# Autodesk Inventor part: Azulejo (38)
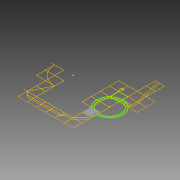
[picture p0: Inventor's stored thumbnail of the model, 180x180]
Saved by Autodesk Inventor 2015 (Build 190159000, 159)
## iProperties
Created: 2015-04
Part Number: Azulejo (38)
Material: Genérico
Document SubType Name: Modeling
Designer: Felipe
Density: 1 g/cm^3
Appearance: Padrão
Author: Felipe
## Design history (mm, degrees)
sketch "Sketch1"
  geometry: L1 (-1510, -7490)-(-1510, -6010); L2 (-3010, -1490)-(-3010, -10); L3 (-2990, 10)-(-1510, 10); L4 (-1510, -10)-(-2990, -10); L5 (-1510, -1490)-(-1510, -10); L6 (-1490, -10)-(-1490, -1490); L7 (-1490, -1490)-(-10, -1490); L8 (-10, -1510)-(-1490, -1510); L9 (-10, -2990)-(-10, -1510); L10 (-10, -5990)-(-10, -4510); L11 (-1490, -7490)-(-10, -7490); L12 (4490, -6010)-(3010, -6010); L13 (10, -1510)-(10, -2990); L14 (10, -3010)-(10, -4490); L15 (10, -4510)-(10, -5990); L16 (10, -5990)-(1490, -5990); L17 (1490, -6010)-(10, -6010); L18 (10, -7490)-(1490, -7490); L19 (1510, -5990)-(2990, -5990); L20 (2990, -6010)-(1510, -6010); L21 (1510, -7490)-(2990, -7490); L22 (4490, 1510)-(4490, 2990); L23 (4490, 10)-(4490, 1490); L24 (4490, -1490)-(4490, -10); L25 (4490, -2990)-(4490, -1510); L26 (3010, -5990)-(4490, -5990); L27 (3010, -7490)-(4490, -7490); L28 (4510, 3010)-(5990, 3010); L29 (5990, 2990)-(4510, 2990); L30 (4510, 2990)-(4510, 1510); L31 (4510, 1510)-(5990, 1510); L32 (5990, 1510)-(5990, 1740.185); L33 (5990, 1760.2)-(5990, 2259.8); L34 (5990, 2279.815)-(5990, 2990); L35 (5990, 1490)-(4510, 1490); L36 (4510, 1490)-(4510, 10); L37 (4510, 10)-(5990, 10); L38 (5990, 10)-(5990, 1490); L39 (5975.983, -10)-(4510, -10); L40 (4510, -10)-(4510, -1490); L41 (5990, -1510)-(5782.897, -1510); L42 (5782.897, -1510)-(5688.66, -1510); L43 (5668.66, -1510)-(5482.895, -1510); L44 (5482.895, -1510)-(5388.656, -1510); L45 (5368.656, -1510)-(4510, -1510); L46 (4510, -1510)-(4510, -2990); L47 (4510, -2990)-(5975.983, -2990); L48 (5990, -2975.728)-(5990, -2837.377); L49 (5990, -2837.377)-(5990, -2536.247); L50 (5990, -2500.476)-(5990, -2317.632); L51 (5990, -2317.632)-(5990, -1510); L52 (5990, -3010)-(4510, -3010); L53 (5990, -4490)-(5990, -3010); L54 (4510, -5990)-(5990, -5990); L55 (5990, -5990)-(5990, -4510); L56 (4510, -7490)-(5990, -7490); L57 (5990, -7490)-(5990, -6310); L58 (5990, -6290)-(5990, -6010); L59 (7490, 4510)-(7490, 5990); L60 (6010, 3010)-(7490, 3010); L61 (7490, 3010)-(7490, 4490); L62 (7490, 2990)-(6010, 2990); L63 (6010, 2990)-(6010, 2279.815); L64 (6010, 2259.8)-(6010, 1760.2)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; A1 r 250 centre (6000, 2010) between (5990, 2259.8) and (5990, 1760.2); A2 r 250 centre (6000, 2010) between (6010, 1760.2) and (6010, 2259.8); A3 r 270 centre (6000, 2010) between (5990, 2279.815) and (5990, 1740.185); A4 r 270 centre (6000, 2010) between (6010, 1740.185) and (6010, 2279.815); A5 r 3010.017 centre (0, 0) between (-1490, -2615.358) and (-346.554, -2990); A6 r 2990.017 centre (0, 0) between (-1490, -2592.316) and (-10, -2990); A7 r 3010.017 centre (0, 0) between (-2603.863, -1510) and (-1510, -2603.863); A8 r 2990.017 centre (0, 0) between (-2580.717, -1510) and (-1510, -2580.717); A9 r 3010.017 centre (0, 0) between (-2990, -346.554) and (-2615.358, -1490); A10 r 2990.017 centre (0, 0) between (-2990, -10) and (-2592.316, -1490); A11 r 2131.367 centre (7500, -1500) between (7490, 631.344) and (6010, 24.017); A12 r 2131.367 centre (7500, -1500) between (5975.983, -10) and (5368.656, -1490); A13 r 2131.367 centre (7500, -1500) between (5368.656, -1510) and (5975.983, -2990); A14 r 2131.367 centre (7500, -1500) between (6010, -3024.017) and (7190, -3608.703); A15 r 1831.367 centre (7500, -1500) between (7490.321, 331.342) and (6463.753, 10); A16 r 1831.367 centre (7500, -1500) between (7489.976, 331.34) and (6010, -435.196); A17 r 1831.367 centre (7500, -1500) between (5990, -463.753) and (5668.66, -1490); A18 r 1831.367 centre (7500, -1500) between (5668.66, -1510) and (5990, -2536.247); A19 r 1831.367 centre (7500, -1500) between (6010, -2564.804) and (6435.196, -2990); A20 r 1831.367 centre (7500, -1500) between (6463.753, -3010) and (7490, -3331.34); A21 r 2111.367 centre (7500, -1500) between (7490.389, 611.346) and (6024.272, 10); A22 r 2111.367 centre (7500, -1500) between (5990, -24.272) and (5388.656, -1490); A23 r 2111.367 centre (7500, -1500) between (5388.656, -1510) and (5990, -2975.728); A24 r 2111.367 centre (7500, -1500) between (6024.272, -3010) and (7210, -3591.357); A25 r 1811.367 centre (7499.986, -1499.91) between (7490.524, 311.432) and (6499.51, 10.09); A26 r 1811.367 centre (7500, -1500) between (6469.975, -10) and (6010, -469.975); A27 r 1811.367 centre (7500, -1500) between (5990, -499.524) and (5688.66, -1490); A28 r 1811.367 centre (7500, -1500) between (5688.66, -1510) and (5990, -2500.476); A29 r 1811.367 centre (7500, -1500) between (6010, -2530.025) and (6469.975, -2990); A30 r 1811.367 centre (7500, -1500) between (6499.524, -3010) and (7490, -3311.34); A31 r 449.871 centre (7499.449, -4060.672) between (7510, -4510.419) and (7521.546, -4510); A32 r 2111.367 centre (7500, -1500) between (7490.019, 611.344) and (7490.389, 611.346); A33 r 1831.367 centre (7500, -1500) between (7489.976, 331.34) and (7490.321, 331.342); A34 r 1811.367 centre (7499.986, -1499.91) between (7489.986, 311.429) and (7490.524, 311.432); A35 r 2131.367 centre (7500, -1500) between (7510, -3631.344) and (7190, -3608.703); A36 r 2131.367 centre (7500, -1500) between (7210, -3611.546) and (7490, -3631.344); 11 further points
  constraints: 718 end point, 82 point on circle, 36 centre point, 14 point on line, 3 concentric, 2 parallel, 2 perpendicular, 1 collinear, 1 horizontal, 1 vertical, 1 other
extrude "Extrusion1" new body sketch "Sketch1" distance "d0" = 60; taper "d1" = 0 deg
extrude "Extrusion2" new body sketch "Sketch1" distance "d2" = 60; taper "d3" = 0 deg
extrude "Extrusion3" new body sketch "Sketch1" distance "d4" = 60; taper "d5" = 0 deg
extrude "Extrusion4" new body sketch "Sketch1" distance "d6" = 60; taper "d7" = 0 deg
body "Solid1"
body "Solid2"
body "Solid3"
body "Solid4"
